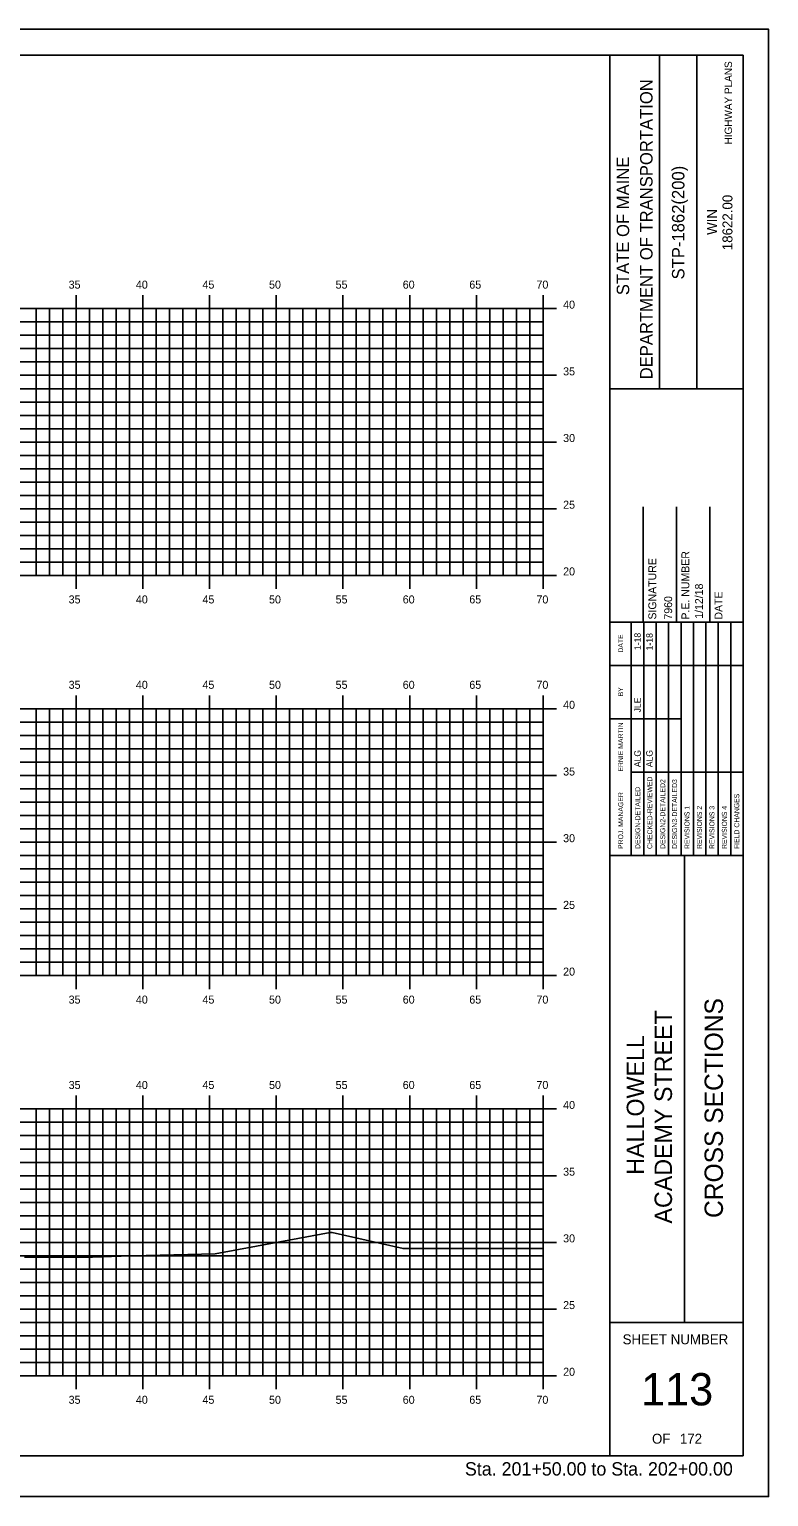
# Model space of a CAD drawing. Extents: x 1023905 to 1024075, y 394697 to 394807.
# Drawn here: x 1024019.2 to 1024074.6, y 394696.5 to 394806.5 of the extents above; entities that cross this region are included whole.
import ezdxf

# ---------------------------------------------------------------- set-up
doc = ezdxf.new("R2010")
doc.units = 0
for name, color, linetype in [('BORDER', 7, 'Continuous'), ('H_V ANNOTATION', 7, 'Continuous'), ('HIGHWAY_TITLE', 7, 'Continuous'), ('MAJOR', 7, 'Continuous'), ('MINOR', 7, 'Continuous'), ('PLOT BOUNDARY', 7, 'Continuous'), ('S_Roadway_Centerline', 7, 'Continuous')]:
    doc.layers.add(name, color=color, linetype=linetype)

msp = doc.modelspace()

# ---------------------------------------------------------------- linework, layer by layer
at = {"layer": 'BORDER'}
for p, q in [((1024072.67, 394804.61), (1023912.67, 394804.61)), ((1024062.67, 394699.61), (1024062.67, 394804.61)), ((1024066.4, 394779.6), (1024066.4, 394804.6)), ((1024069.19, 394779.6), (1024069.19, 394804.6)), ((1024072.67, 394699.61), (1024072.67, 394804.61)), ((1024062.67, 394779.6), (1024072.67, 394779.6)), ((1024065.17, 394762.11), (1024065.17, 394770.76)), ((1024067.67, 394762.11), (1024067.67, 394770.76)), ((1024070.17, 394762.11), (1024070.17, 394770.76)), ((1024062.67, 394762.11), (1024072.67, 394762.11)), ((1024062.67, 394744.61), (1024072.67, 394744.61)), ((1024068.26, 394709.61), (1024068.26, 394744.61)), ((1024062.67, 394709.61), (1024072.67, 394709.61)), ((1023912.67, 394699.61), (1024072.67, 394699.61))]:
    msp.add_line(p, q, dxfattribs=at)
for points in [[(1024064.28, 394758.86), (1024064.28, 394762.11)], [(1024064.28, 394744.61), (1024064.28, 394761.4)], [(1024065.21, 394744.61), (1024065.21, 394762.11)], [(1024066.15, 394762.11), (1024066.15, 394744.61)], [(1024067.08, 394744.61), (1024067.08, 394762.11)], [(1024068.01, 394744.61), (1024068.01, 394762.11)], [(1024068.94, 394744.61), (1024068.94, 394762.11)], [(1024069.87, 394744.61), (1024069.87, 394762.11)], [(1024070.8, 394744.61), (1024070.8, 394762.11)], [(1024071.74, 394744.61), (1024071.74, 394762.11)], [(1024062.67, 394758.86), (1024072.67, 394758.86)], [(1024062.67, 394754.86), (1024064.28, 394754.86)], [(1024064.28, 394754.86), (1024068.01, 394754.86)], [(1024064.28, 394750.86), (1024072.67, 394750.86)]]:
    msp.add_lwpolyline(points, dxfattribs=at)
at = {"layer": 'MAJOR'}
for p, q in [((1023917.67, 394785.61), (1024057.67, 394785.61)), ((1024022.67, 394786.61), (1024022.67, 394785.61)), ((1024022.67, 394765.61), (1024022.67, 394785.61)), ((1024027.67, 394786.61), (1024027.67, 394785.61)), ((1024027.67, 394765.61), (1024027.67, 394785.61)), ((1024032.67, 394786.61), (1024032.67, 394785.61)), ((1024032.67, 394765.61), (1024032.67, 394785.61)), ((1024037.67, 394786.61), (1024037.67, 394785.61)), ((1024037.67, 394765.61), (1024037.67, 394785.61)), ((1024042.67, 394786.61), (1024042.67, 394785.61)), ((1024042.67, 394765.61), (1024042.67, 394785.61)), ((1024047.67, 394786.61), (1024047.67, 394785.61)), ((1024047.67, 394765.61), (1024047.67, 394785.61)), ((1024052.67, 394786.61), (1024052.67, 394785.61)), ((1024052.67, 394765.61), (1024052.67, 394785.61)), ((1024058.67, 394785.61), (1024056.66, 394785.61)), ((1024057.67, 394786.61), (1024057.67, 394785.61)), ((1024057.67, 394765.61), (1024057.67, 394785.61)), ((1023917.67, 394780.61), (1024057.67, 394780.61)), ((1024058.67, 394780.61), (1024056.66, 394780.61)), ((1023917.67, 394775.61), (1024057.67, 394775.61)), ((1024058.67, 394775.61), (1024056.66, 394775.61)), ((1023917.67, 394770.61), (1024057.67, 394770.61)), ((1024058.67, 394770.61), (1024056.66, 394770.61)), ((1023917.67, 394765.61), (1024057.67, 394765.61)), ((1024022.67, 394764.6), (1024022.67, 394765.61)), ((1024027.67, 394764.6), (1024027.67, 394765.61)), ((1024032.67, 394764.6), (1024032.67, 394765.61)), ((1024037.67, 394764.6), (1024037.67, 394765.61)), ((1024042.67, 394764.6), (1024042.67, 394765.61)), ((1024047.67, 394764.6), (1024047.67, 394765.61)), ((1024052.67, 394764.6), (1024052.67, 394765.61)), ((1024058.67, 394765.61), (1024056.66, 394765.61)), ((1024057.67, 394764.6), (1024057.67, 394765.61)), ((1024022.67, 394756.61), (1024022.67, 394755.61)), ((1024027.67, 394756.61), (1024027.67, 394755.61)), ((1024032.67, 394756.61), (1024032.67, 394755.61)), ((1024037.67, 394756.61), (1024037.67, 394755.61)), ((1024042.67, 394756.61), (1024042.67, 394755.61)), ((1024047.67, 394756.61), (1024047.67, 394755.61)), ((1024052.67, 394756.61), (1024052.67, 394755.61)), ((1024057.67, 394756.61), (1024057.67, 394755.61)), ((1023917.67, 394755.61), (1024057.67, 394755.61)), ((1024022.67, 394735.61), (1024022.67, 394755.61)), ((1024027.67, 394735.61), (1024027.67, 394755.61)), ((1024032.67, 394735.61), (1024032.67, 394755.61)), ((1024037.67, 394735.61), (1024037.67, 394755.61)), ((1024042.67, 394735.61), (1024042.67, 394755.61)), ((1024047.67, 394735.61), (1024047.67, 394755.61)), ((1024052.67, 394735.61), (1024052.67, 394755.61)), ((1024058.67, 394755.61), (1024056.66, 394755.61)), ((1024057.67, 394735.61), (1024057.67, 394755.61)), ((1023917.67, 394750.61), (1024057.67, 394750.61)), ((1024058.67, 394750.61), (1024056.66, 394750.61)), ((1023917.67, 394745.61), (1024057.67, 394745.61)), ((1024058.67, 394745.61), (1024056.66, 394745.61)), ((1023917.67, 394740.61), (1024057.67, 394740.61)), ((1024058.67, 394740.61), (1024056.66, 394740.61)), ((1023917.67, 394735.61), (1024057.67, 394735.61)), ((1024022.67, 394734.6), (1024022.67, 394735.61)), ((1024027.67, 394734.6), (1024027.67, 394735.61)), ((1024032.67, 394734.6), (1024032.67, 394735.61)), ((1024037.67, 394734.6), (1024037.67, 394735.61)), ((1024042.67, 394734.6), (1024042.67, 394735.61)), ((1024047.67, 394734.6), (1024047.67, 394735.61)), ((1024052.67, 394734.6), (1024052.67, 394735.61)), ((1024058.67, 394735.61), (1024056.66, 394735.61)), ((1024057.67, 394734.6), (1024057.67, 394735.61)), ((1024022.67, 394726.61), (1024022.67, 394725.61)), ((1024027.67, 394726.61), (1024027.67, 394725.61)), ((1024032.67, 394726.61), (1024032.67, 394725.61)), ((1024037.67, 394726.61), (1024037.67, 394725.61)), ((1024042.67, 394726.61), (1024042.67, 394725.61)), ((1024047.67, 394726.61), (1024047.67, 394725.61)), ((1024052.67, 394726.61), (1024052.67, 394725.61)), ((1024057.67, 394726.61), (1024057.67, 394725.61)), ((1023917.67, 394725.61), (1024057.67, 394725.61)), ((1024022.67, 394705.61), (1024022.67, 394725.61)), ((1024027.67, 394705.61), (1024027.67, 394725.61)), ((1024032.67, 394705.61), (1024032.67, 394725.61)), ((1024037.67, 394705.61), (1024037.67, 394725.61)), ((1024042.67, 394705.61), (1024042.67, 394725.61)), ((1024047.67, 394705.61), (1024047.67, 394725.61)), ((1024052.67, 394705.61), (1024052.67, 394725.61)), ((1024058.67, 394725.61), (1024056.66, 394725.61)), ((1024057.67, 394705.61), (1024057.67, 394725.61)), ((1023917.67, 394720.61), (1024057.67, 394720.61)), ((1024058.67, 394720.61), (1024056.66, 394720.61)), ((1023917.67, 394715.61), (1024057.67, 394715.61)), ((1024058.67, 394715.61), (1024056.66, 394715.61)), ((1023917.67, 394710.61), (1024057.67, 394710.61)), ((1024058.67, 394710.61), (1024056.66, 394710.61)), ((1023917.67, 394705.61), (1024057.67, 394705.61)), ((1024022.67, 394704.6), (1024022.67, 394705.61)), ((1024027.67, 394704.6), (1024027.67, 394705.61)), ((1024032.67, 394704.6), (1024032.67, 394705.61)), ((1024037.67, 394704.6), (1024037.67, 394705.61)), ((1024042.67, 394704.6), (1024042.67, 394705.61)), ((1024047.67, 394704.6), (1024047.67, 394705.61)), ((1024052.67, 394704.6), (1024052.67, 394705.61)), ((1024058.67, 394705.61), (1024056.66, 394705.61)), ((1024057.67, 394704.6), (1024057.67, 394705.61))]:
    msp.add_line(p, q, dxfattribs=at)
at = {"layer": 'MINOR'}
for p, q in [((1024019.67, 394765.61), (1024019.67, 394785.61)), ((1024020.67, 394765.61), (1024020.67, 394785.61)), ((1024021.67, 394765.61), (1024021.67, 394785.61)), ((1024023.67, 394765.61), (1024023.67, 394785.61)), ((1024024.67, 394765.61), (1024024.67, 394785.61)), ((1024025.67, 394765.61), (1024025.67, 394785.61)), ((1024026.67, 394765.61), (1024026.67, 394785.61)), ((1024028.67, 394765.61), (1024028.67, 394785.61)), ((1024029.67, 394765.61), (1024029.67, 394785.61)), ((1024030.67, 394765.61), (1024030.67, 394785.61)), ((1024031.67, 394765.61), (1024031.67, 394785.61)), ((1024033.67, 394765.61), (1024033.67, 394785.61)), ((1024034.67, 394765.61), (1024034.67, 394785.61)), ((1024035.67, 394765.61), (1024035.67, 394785.61)), ((1024036.67, 394765.61), (1024036.67, 394785.61)), ((1024038.67, 394765.61), (1024038.67, 394785.61)), ((1024039.67, 394765.61), (1024039.67, 394785.61)), ((1024040.67, 394765.61), (1024040.67, 394785.61)), ((1024041.67, 394765.61), (1024041.67, 394785.61)), ((1024043.67, 394765.61), (1024043.67, 394785.61)), ((1024044.67, 394765.61), (1024044.67, 394785.61)), ((1024045.67, 394765.61), (1024045.67, 394785.61)), ((1024046.67, 394765.61), (1024046.67, 394785.61)), ((1024048.67, 394765.61), (1024048.67, 394785.61)), ((1024049.67, 394765.61), (1024049.67, 394785.61)), ((1024050.67, 394765.61), (1024050.67, 394785.61)), ((1024051.67, 394765.61), (1024051.67, 394785.61)), ((1024053.67, 394765.61), (1024053.67, 394785.61)), ((1024054.67, 394765.61), (1024054.67, 394785.61)), ((1024055.67, 394765.61), (1024055.67, 394785.61)), ((1024056.67, 394765.61), (1024056.67, 394785.61)), ((1023917.67, 394784.61), (1024057.67, 394784.61)), ((1024057.67, 394784.61), (1024056.66, 394784.61)), ((1023917.67, 394783.61), (1024057.67, 394783.61)), ((1024057.67, 394783.61), (1024056.66, 394783.61)), ((1023917.67, 394782.61), (1024057.67, 394782.61)), ((1024057.67, 394782.61), (1024056.66, 394782.61)), ((1023917.67, 394781.61), (1024057.67, 394781.61)), ((1024057.67, 394781.61), (1024056.66, 394781.61)), ((1023917.67, 394779.61), (1024057.67, 394779.61)), ((1024057.67, 394779.61), (1024056.66, 394779.61)), ((1023917.67, 394778.61), (1024057.67, 394778.61)), ((1024057.67, 394778.61), (1024056.66, 394778.61)), ((1023917.67, 394777.61), (1024057.67, 394777.61)), ((1024057.67, 394777.61), (1024056.66, 394777.61)), ((1023917.67, 394776.61), (1024057.67, 394776.61)), ((1024057.67, 394776.61), (1024056.66, 394776.61)), ((1023917.67, 394774.61), (1024057.67, 394774.61)), ((1024057.67, 394774.61), (1024056.66, 394774.61)), ((1023917.67, 394773.61), (1024057.67, 394773.61)), ((1024057.67, 394773.61), (1024056.66, 394773.61)), ((1023917.67, 394772.61), (1024057.67, 394772.61)), ((1024057.67, 394772.61), (1024056.66, 394772.61)), ((1023917.67, 394771.61), (1024057.67, 394771.61)), ((1024057.67, 394771.61), (1024056.66, 394771.61)), ((1023917.67, 394769.61), (1024057.67, 394769.61)), ((1024057.67, 394769.61), (1024056.66, 394769.61)), ((1023917.67, 394768.61), (1024057.67, 394768.61)), ((1024057.67, 394768.61), (1024056.66, 394768.61)), ((1023917.67, 394767.61), (1024057.67, 394767.61)), ((1024057.67, 394767.61), (1024056.66, 394767.61)), ((1023917.67, 394766.61), (1024057.67, 394766.61)), ((1024057.67, 394766.61), (1024056.66, 394766.61)), ((1024019.67, 394735.61), (1024019.67, 394755.61)), ((1024020.67, 394735.61), (1024020.67, 394755.61)), ((1024021.67, 394735.61), (1024021.67, 394755.61)), ((1024023.67, 394735.61), (1024023.67, 394755.61)), ((1024024.67, 394735.61), (1024024.67, 394755.61)), ((1024025.67, 394735.61), (1024025.67, 394755.61)), ((1024026.67, 394735.61), (1024026.67, 394755.61)), ((1024028.67, 394735.61), (1024028.67, 394755.61)), ((1024029.67, 394735.61), (1024029.67, 394755.61)), ((1024030.67, 394735.61), (1024030.67, 394755.61)), ((1024031.67, 394735.61), (1024031.67, 394755.61)), ((1024033.67, 394735.61), (1024033.67, 394755.61)), ((1024034.67, 394735.61), (1024034.67, 394755.61)), ((1024035.67, 394735.61), (1024035.67, 394755.61)), ((1024036.67, 394735.61), (1024036.67, 394755.61)), ((1024038.67, 394735.61), (1024038.67, 394755.61)), ((1024039.67, 394735.61), (1024039.67, 394755.61)), ((1024040.67, 394735.61), (1024040.67, 394755.61)), ((1024041.67, 394735.61), (1024041.67, 394755.61)), ((1024043.67, 394735.61), (1024043.67, 394755.61)), ((1024044.67, 394735.61), (1024044.67, 394755.61)), ((1024045.67, 394735.61), (1024045.67, 394755.61)), ((1024046.67, 394735.61), (1024046.67, 394755.61)), ((1024048.67, 394735.61), (1024048.67, 394755.61)), ((1024049.67, 394735.61), (1024049.67, 394755.61)), ((1024050.67, 394735.61), (1024050.67, 394755.61)), ((1024051.67, 394735.61), (1024051.67, 394755.61)), ((1024053.67, 394735.61), (1024053.67, 394755.61)), ((1024054.67, 394735.61), (1024054.67, 394755.61)), ((1024055.67, 394735.61), (1024055.67, 394755.61)), ((1024056.67, 394735.61), (1024056.67, 394755.61)), ((1023917.67, 394754.61), (1024057.67, 394754.61)), ((1024057.67, 394754.61), (1024056.66, 394754.61)), ((1023917.67, 394753.61), (1024057.67, 394753.61)), ((1023917.67, 394752.61), (1024057.67, 394752.61)), ((1024057.67, 394753.61), (1024056.66, 394753.61)), ((1024057.67, 394752.61), (1024056.66, 394752.61)), ((1023917.67, 394751.61), (1024057.67, 394751.61)), ((1024057.67, 394751.61), (1024056.66, 394751.61)), ((1023917.67, 394749.61), (1024057.67, 394749.61)), ((1024057.67, 394749.61), (1024056.66, 394749.61)), ((1023917.67, 394748.61), (1024057.67, 394748.61)), ((1024057.67, 394748.61), (1024056.66, 394748.61)), ((1023917.67, 394747.61), (1024057.67, 394747.61)), ((1024057.67, 394747.61), (1024056.66, 394747.61)), ((1023917.67, 394746.61), (1024057.67, 394746.61)), ((1024057.67, 394746.61), (1024056.66, 394746.61)), ((1023917.67, 394744.61), (1024057.67, 394744.61)), ((1024057.67, 394744.61), (1024056.66, 394744.61)), ((1023917.67, 394743.61), (1024057.67, 394743.61)), ((1024057.67, 394743.61), (1024056.66, 394743.61)), ((1023917.67, 394742.61), (1024057.67, 394742.61)), ((1023917.67, 394741.61), (1024057.67, 394741.61)), ((1024057.67, 394742.61), (1024056.66, 394742.61)), ((1024057.67, 394741.61), (1024056.66, 394741.61)), ((1023917.67, 394739.61), (1024057.67, 394739.61)), ((1024057.67, 394739.61), (1024056.66, 394739.61)), ((1023917.67, 394738.61), (1024057.67, 394738.61)), ((1024057.67, 394738.61), (1024056.66, 394738.61)), ((1023917.67, 394737.61), (1024057.67, 394737.61)), ((1024057.67, 394737.61), (1024056.66, 394737.61)), ((1023917.67, 394736.61), (1024057.67, 394736.61)), ((1024057.67, 394736.61), (1024056.66, 394736.61)), ((1024019.67, 394705.61), (1024019.67, 394725.61)), ((1024020.67, 394705.61), (1024020.67, 394725.61)), ((1024021.67, 394705.61), (1024021.67, 394725.61)), ((1024023.67, 394705.61), (1024023.67, 394725.61)), ((1024024.67, 394705.61), (1024024.67, 394725.61)), ((1024025.67, 394705.61), (1024025.67, 394725.61)), ((1024026.67, 394705.61), (1024026.67, 394725.61)), ((1024028.67, 394705.61), (1024028.67, 394725.61)), ((1024029.67, 394705.61), (1024029.67, 394725.61)), ((1024030.67, 394705.61), (1024030.67, 394725.61)), ((1024031.67, 394705.61), (1024031.67, 394725.61)), ((1024033.67, 394705.61), (1024033.67, 394725.61)), ((1024034.67, 394705.61), (1024034.67, 394725.61)), ((1024035.67, 394705.61), (1024035.67, 394725.61)), ((1024036.67, 394705.61), (1024036.67, 394725.61)), ((1024038.67, 394705.61), (1024038.67, 394725.61)), ((1024039.67, 394705.61), (1024039.67, 394725.61)), ((1024040.67, 394705.61), (1024040.67, 394725.61)), ((1024041.67, 394705.61), (1024041.67, 394725.61)), ((1024043.67, 394705.61), (1024043.67, 394725.61)), ((1024044.67, 394705.61), (1024044.67, 394725.61)), ((1024045.67, 394705.61), (1024045.67, 394725.61)), ((1024046.67, 394705.61), (1024046.67, 394725.61)), ((1024048.67, 394705.61), (1024048.67, 394725.61)), ((1024049.67, 394705.61), (1024049.67, 394725.61)), ((1024050.67, 394705.61), (1024050.67, 394725.61)), ((1024051.67, 394705.61), (1024051.67, 394725.61)), ((1024053.67, 394705.61), (1024053.67, 394725.61)), ((1024054.67, 394705.61), (1024054.67, 394725.61)), ((1024055.67, 394705.61), (1024055.67, 394725.61)), ((1024056.67, 394705.61), (1024056.67, 394725.61)), ((1023917.67, 394724.61), (1024057.67, 394724.61)), ((1024057.67, 394724.61), (1024056.66, 394724.61)), ((1023917.67, 394723.61), (1024057.67, 394723.61)), ((1024057.67, 394723.61), (1024056.66, 394723.61)), ((1023917.67, 394722.61), (1024057.67, 394722.61)), ((1024057.67, 394722.61), (1024056.66, 394722.61)), ((1023917.67, 394721.61), (1024057.67, 394721.61)), ((1024057.67, 394721.61), (1024056.66, 394721.61)), ((1023917.67, 394719.61), (1024057.67, 394719.61)), ((1024057.67, 394719.61), (1024056.66, 394719.61)), ((1023917.67, 394718.61), (1024057.67, 394718.61)), ((1024057.67, 394718.61), (1024056.66, 394718.61)), ((1023917.67, 394717.61), (1024057.67, 394717.61)), ((1024057.67, 394717.61), (1024056.66, 394717.61)), ((1023917.67, 394716.61), (1024057.67, 394716.61)), ((1024057.67, 394716.61), (1024056.66, 394716.61)), ((1023917.67, 394714.61), (1024057.67, 394714.61)), ((1024057.67, 394714.61), (1024056.66, 394714.61)), ((1023917.67, 394713.61), (1024057.67, 394713.61)), ((1024057.67, 394713.61), (1024056.66, 394713.61)), ((1023917.67, 394712.61), (1024057.67, 394712.61)), ((1024057.67, 394712.61), (1024056.66, 394712.61)), ((1023917.67, 394711.61), (1024057.67, 394711.61)), ((1024057.67, 394711.61), (1024056.66, 394711.61)), ((1023917.67, 394709.61), (1024057.67, 394709.61)), ((1023917.67, 394708.61), (1024057.67, 394708.61)), ((1024057.67, 394709.61), (1024056.66, 394709.61)), ((1024057.67, 394708.61), (1024056.66, 394708.61)), ((1023917.67, 394707.61), (1024057.67, 394707.61)), ((1024057.67, 394707.61), (1024056.66, 394707.61)), ((1023917.67, 394706.61), (1024057.67, 394706.61)), ((1024057.67, 394706.61), (1024056.66, 394706.61))]:
    msp.add_line(p, q, dxfattribs=at)
at = {"layer": 'PLOT BOUNDARY'}
msp.add_lwpolyline([(1023904.57, 394696.55), (1024074.57, 394696.55), (1024074.57, 394806.55), (1023904.57, 394806.55)], close=True, dxfattribs=at)
at = {"layer": 'S_Roadway_Centerline'}
msp.add_lwpolyline([(1024018.8, 394714.49), (1024023.91, 394714.51), (1024026.05, 394714.57), (1024026.9, 394714.59), (1024032.06, 394714.72), (1024033.09, 394714.75), (1024041.71, 394716.36), (1024041.75, 394716.36), (1024041.85, 394716.36), (1024047.17, 394715.14), (1024057.67, 394715.14)], dxfattribs=at)

# ---------------------------------------------------------------- texts
at = {"layer": 'BORDER'}
for s, height, rotation, p in [('DEPARTMENT OF TRANSPORTATION', 0.9318, 90, (1024065.87, 394780.31)), ('STATE OF MAINE', 0.9318, 90, (1024064.12, 394786.62)), ('STP-1862(200)', 0.9318, 90, (1024068.26, 394787.8)), ('18622.00', 0.745, 90, (1024071.86, 394789.99)), ('WIN', 0.745, 90, (1024070.7, 394791.14)), ('P.E. NUMBER', 0.5906, 90, (1024068.63, 394762.3)), ('SIGNATURE', 0.591, 90, (1024066.15, 394762.3)), ('1/12/18', 0.591, 90, (1024069.65, 394762.36)), ('7960', 0.591, 90, (1024067.34, 394762.3)), ('DATE', 0.591, 90, (1024071.11, 394762.3)), ('DATE', 0.371, 90, (1024063.67, 394759.82)), ('1-18', 0.485, 90, (1024064.99, 394760.01)), ('1-18', 0.485, 90, (1024065.88, 394759.99)), ('BY', 0.371, 90, (1024063.67, 394756.54)), ('JLE', 0.485, 90, (1024064.99, 394755.34)), ('ERNIE MARTIN', 0.3727, 90, (1024063.67, 394750.9)), ('ALG', 0.485, 90, (1024064.99, 394751.23)), ('ALG', 0.485, 90, (1024065.88, 394751.23)), ('DESIGN-DETAILED', 0.3727, 90, (1024064.95, 394745.1)), ('CHECKED-REVIEWED', 0.3727, 90, (1024065.85, 394745.1)), ('DESIGN2-DETAILED2', 0.3727, 90, (1024066.82, 394745.1)), ('DESIGN3-DETAILED3', 0.3727, 90, (1024067.71, 394745.1)), ('PROJ. MANAGER', 0.3727, 90, (1024063.67, 394745.1)), ('REVISIONS 1', 0.3727, 90, (1024068.64, 394745.1)), ('REVISIONS 2', 0.3727, 90, (1024069.57, 394745.1)), ('REVISIONS 3', 0.3727, 90, (1024070.51, 394745.1)), ('REVISIONS 4', 0.3727, 90, (1024071.44, 394745.1)), ('FIELD CHANGES', 0.3727, 90, (1024072.37, 394745.1)), ('CROSS SECTIONS', 1.3779, 90, (1024071.15, 394717.44)), ('SHEET NUMBER', 0.7453, 360, (1024063.63, 394707.97)), ('113', 2.419, 360, (1024065.02, 394703.39)), ('OF', 0.745, 360, (1024065.83, 394700.52)), ('172', 0.745, 360, (1024067.92, 394700.52))]:
    msp.add_text(s, height=height, rotation=rotation, dxfattribs=at).set_placement(p)
at = {"layer": 'H_V ANNOTATION'}
for s, height, p in [('35', 0.6, (1024022.11, 394787.11)), ('40', 0.6, (1024027.15, 394787.11)), ('45', 0.6, (1024032.14, 394787.11)), ('50', 0.6, (1024037.13, 394787.11)), ('55', 0.6, (1024042.12, 394787.11)), ('60', 0.6, (1024047.15, 394787.11)), ('65', 0.6, (1024052.14, 394787.11)), ('70', 0.6, (1024057.17, 394787.11)), ('40', 0.6, (1024059.17, 394785.61)), ('35', 0.6, (1024059.17, 394780.61)), ('30', 0.6, (1024059.17, 394775.61)), ('25', 0.6, (1024059.17, 394770.61)), ('20', 0.6, (1024059.17, 394765.61)), ('35', 0.6, (1024022.11, 394763.51)), ('40', 0.6, (1024027.15, 394763.51)), ('45', 0.6, (1024032.14, 394763.51)), ('50', 0.6, (1024037.13, 394763.51)), ('55', 0.6, (1024042.12, 394763.51)), ('60', 0.6, (1024047.15, 394763.51)), ('65', 0.6, (1024052.14, 394763.51)), ('70', 0.6, (1024057.17, 394763.51)), ('35', 0.6, (1024022.11, 394757.11)), ('40', 0.6, (1024027.15, 394757.11)), ('45', 0.6, (1024032.14, 394757.11)), ('50', 0.6, (1024037.13, 394757.11)), ('55', 0.6, (1024042.12, 394757.11)), ('60', 0.6, (1024047.15, 394757.11)), ('65', 0.6, (1024052.14, 394757.11)), ('70', 0.6, (1024057.17, 394757.11)), ('40', 0.6, (1024059.17, 394755.61)), ('35', 0.6, (1024059.17, 394750.61)), ('30', 0.6, (1024059.17, 394745.61)), ('25', 0.6, (1024059.17, 394740.61)), ('20', 0.6, (1024059.17, 394735.61)), ('35', 0.6, (1024022.11, 394733.51)), ('40', 0.6, (1024027.15, 394733.51)), ('45', 0.6, (1024032.14, 394733.51)), ('50', 0.6, (1024037.13, 394733.51)), ('55', 0.6, (1024042.12, 394733.51)), ('60', 0.6, (1024047.15, 394733.51)), ('65', 0.6, (1024052.14, 394733.51)), ('70', 0.6, (1024057.17, 394733.51)), ('35', 0.6, (1024022.11, 394727.11)), ('40', 0.6, (1024027.15, 394727.11)), ('45', 0.6, (1024032.14, 394727.11)), ('50', 0.6, (1024037.13, 394727.11)), ('55', 0.6, (1024042.12, 394727.11)), ('60', 0.6, (1024047.15, 394727.11)), ('65', 0.6, (1024052.14, 394727.11)), ('70', 0.6, (1024057.17, 394727.11)), ('40', 0.6, (1024059.17, 394725.61)), ('35', 0.6, (1024059.17, 394720.61)), ('30', 0.6, (1024059.17, 394715.61)), ('25', 0.6, (1024059.17, 394710.61)), ('20', 0.6, (1024059.17, 394705.61)), ('35', 0.6, (1024022.11, 394703.51)), ('40', 0.6, (1024027.15, 394703.51)), ('45', 0.6, (1024032.14, 394703.51)), ('50', 0.6, (1024037.13, 394703.51)), ('55', 0.6, (1024042.12, 394703.51)), ('60', 0.6, (1024047.15, 394703.51)), ('65', 0.6, (1024052.14, 394703.51)), ('70', 0.6, (1024057.17, 394703.51)), ('Sta. 201+50.00 to Sta. 202+00.00', 1.0002, (1024051.81, 394698.13))]:
    msp.add_text(s, height=height, dxfattribs=at).set_placement(p)
at = {"layer": 'HIGHWAY_TITLE'}
for s, height, p in [('HIGHWAY PLANS', 0.559, (1024071.83, 394797.92)), ('ACADEMY STREET', 1.3043, (1024067.33, 394717.02)), ('HALLOWELL', 1.304, (1024065.24, 394720.68))]:
    msp.add_text(s, height=height, rotation=90, dxfattribs=at).set_placement(p)

doc.saveas('drawing.dxf')
